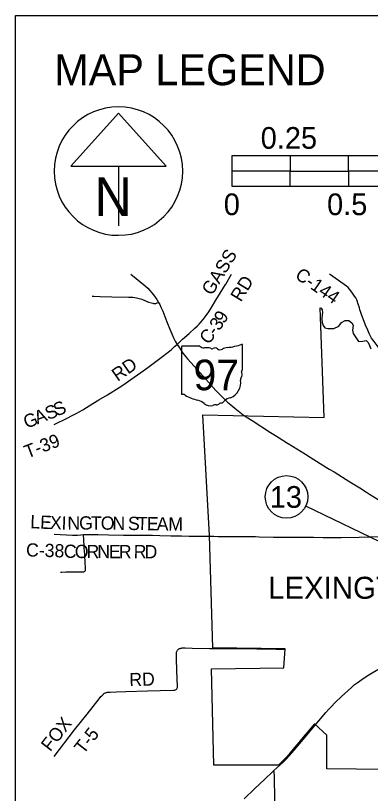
# Model space of a CAD drawing. Extents: x 40529 to 41139, y 15164 to 15584.
# Drawn here: x 40528.7 to 40574.5, y 15483.8 to 15584.3 of the extents above; entities that cross this region are included whole.
import ezdxf

# ---------------------------------------------------------------- set-up
doc = ezdxf.new("R2010")
doc.units = 0
for name, color, linetype in [('GM_X_Corporation', 7, 'Continuous'), ('GM_X_Corporation_Text', 7, 'Continuous'), ('GM_X_County_Road', 7, 'Continuous'), ('GM_X_County_Road_Text', 7, 'Continuous'), ('GM_X_State_Route', 7, 'Continuous'), ('GM_X_State_Shield', 7, 'Continuous'), ('GM_X_Township_Road', 7, 'Continuous'), ('GM_X_Township_Road_Text', 7, 'Continuous'), ('GM_X_US_Route', 7, 'Continuous'), ('SC_Scratch1', 7, 'Continuous'), ('SH_Data', 7, 'Continuous'), ('SH_Text', 7, 'Continuous')]:
    doc.layers.add(name, color=color, linetype=linetype)

msp = doc.modelspace()

# ---------------------------------------------------------------- linework, layer by layer
at = {"layer": 'GM_X_Corporation'}
msp.add_lwpolyline([(40584.23, 15486.79), (40568.88, 15486.95), (40568.88, 15486.95), (40568.88, 15491.32), (40567.29, 15492.76), (40566.61, 15491.95), (40565.83, 15491.04), (40565.06, 15490.12), (40564.72, 15489.71), (40564.14, 15489.02), (40563.75, 15488.56), (40563.04, 15487.84), (40562.64, 15487.43), (40554.28, 15487.42), (40553.97, 15499.9), (40563.32, 15500.01), (40563.49, 15502.49), (40554.13, 15502.61), (40553.72, 15517.1), (40552.87, 15532.73), (40568.54, 15532.36), (40568, 15546.52), (40568.14, 15546.49), (40568.28, 15546.26), (40568.32, 15545.94), (40568.29, 15545.62), (40568.25, 15545.13), (40568.27, 15544.63), (40568.39, 15544.27), (40568.62, 15543.97), (40568.99, 15543.85), (40569.77, 15543.86), (40570.41, 15544.15), (40570.79, 15544.64), (40571.23, 15544.89), (40571.74, 15544.9), (40572.12, 15544.62), (40572.28, 15544.29), (40572.2, 15543.64), (40572.28, 15543.21), (40572.61, 15542.7), (40572.99, 15542.21), (40573.55, 15542.23), (40573.95, 15542.33), (40574.22, 15542.05), (40574.41, 15541.67), (40574.58, 15541.26)], dxfattribs=at)
at = {"layer": 'GM_X_County_Road'}
for p, q in [((40555.82, 15549.61), (40556.58, 15550.88)), ((40568.42, 15516.86), (40569.24, 15516.85))]:
    msp.add_line(p, q, dxfattribs=at)
for points in [[(40573.15, 15546.3), (40573.09, 15546.52), (40572.9, 15547.14), (40572.84, 15547.32), (40572.74, 15547.57), (40572.61, 15547.82), (40572.46, 15548.06), (40572.21, 15548.44), (40571.99, 15548.75), (40571.82, 15548.97), (40571.63, 15549.16), (40571.42, 15549.34), (40571.12, 15549.56), (40569.23, 15550.88)], [(40549.53, 15541.82), (40549.62, 15541.9), (40550.24, 15542.47), (40551.07, 15543.22), (40551.83, 15543.9), (40552.17, 15544.22), (40552.36, 15544.42), (40552.61, 15544.69), (40552.9, 15545.05), (40553.29, 15545.57), (40553.61, 15546.03), (40553.96, 15546.57), (40554.55, 15547.52), (40555.79, 15549.56), (40555.82, 15549.61)], [(40573.89, 15544.31), (40573.71, 15544.76), (40573.41, 15545.55), (40573.22, 15546.07), (40573.15, 15546.3)], [(40575.85, 15540.86), (40575.79, 15541.04), (40575.66, 15541.29), (40575.5, 15541.51), (40574.98, 15542.17), (40574.81, 15542.4), (40574.66, 15542.63), (40574.52, 15542.87), (40574.35, 15543.21), (40574.16, 15543.64), (40573.89, 15544.31)], [(40533.65, 15517.29), (40536.01, 15517.17), (40536.64, 15517.17), (40537.1, 15517.2), (40537.44, 15517.23)], [(40537.44, 15517.23), (40537.74, 15517.23), (40538.33, 15517.23), (40539.32, 15517.23), (40540.65, 15517.19), (40542.6, 15517.18), (40543.83, 15517.17), (40544.89, 15517.16), (40545.26, 15517.16), (40546.36, 15517.14), (40547.3, 15517.12), (40548.72, 15517.09), (40550.09, 15517.07), (40551.08, 15517.04), (40551.67, 15517.03), (40552.31, 15517.03), (40552.88, 15517.02), (40553.71, 15517.01)], [(40553.71, 15517.01), (40553.74, 15517.01), (40554.27, 15517.01), (40554.85, 15517), (40555.51, 15517), (40556.97, 15517)], [(40556.97, 15517), (40557.44, 15516.99), (40558.18, 15516.99), (40559.67, 15516.97), (40560.13, 15516.96), (40562, 15516.92), (40563.92, 15516.9)], [(40563.92, 15516.9), (40565.3, 15516.89), (40567.14, 15516.88), (40568.42, 15516.86)], [(40569.24, 15516.85), (40570.03, 15516.85), (40570.5, 15516.86), (40570.74, 15516.86)], [(40570.74, 15516.86), (40573.06, 15516.91), (40575.97, 15516.98), (40578.14, 15517.02), (40578.62, 15517.04)]]:
    msp.add_lwpolyline(points, dxfattribs=at)
at = {"layer": 'GM_X_State_Route'}
for points in [[(40543.56, 15550.88), (40545.38, 15549.37), (40545.73, 15549.06), (40545.99, 15548.8), (40546.24, 15548.52), (40546.48, 15548.23), (40546.7, 15547.93), (40546.91, 15547.62), (40547.1, 15547.3), (40547.13, 15547.24), (40547.28, 15546.97), (40547.44, 15546.63), (40547.67, 15546.12), (40547.95, 15545.43), (40548.22, 15544.73), (40548.59, 15543.77), (40548.84, 15543.17), (40549.07, 15542.67), (40549.28, 15542.25), (40549.53, 15541.82)], [(40549.53, 15541.82), (40549.66, 15541.61), (40549.91, 15541.22), (40550.17, 15540.83), (40550.45, 15540.46), (40550.87, 15539.96), (40551.3, 15539.47), (40552.11, 15538.57), (40553.23, 15537.32), (40554.54, 15535.87), (40555.12, 15535.26), (40555.65, 15534.74), (40556.05, 15534.35), (40556.47, 15533.99), (40556.97, 15533.57), (40557.63, 15533.05), (40558.08, 15532.72), (40558.46, 15532.46), (40559.21, 15532), (40559.24, 15531.98)], [(40559.24, 15531.98), (40561.61, 15530.44), (40562.02, 15530.18)], [(40562.02, 15530.18), (40562.72, 15529.75), (40563.81, 15529.05), (40563.88, 15529.01), (40565.56, 15527.96), (40566.12, 15527.61)], [(40566.12, 15527.61), (40566.74, 15527.23), (40567.18, 15526.95), (40569.19, 15525.71), (40569.84, 15525.33), (40571.87, 15524.04), (40573.14, 15523.26), (40574, 15522.73), (40574.41, 15522.47), (40576.06, 15521.44), (40576.19, 15521.36)]]:
    msp.add_lwpolyline(points, dxfattribs=at)
at = {"layer": 'GM_X_State_Shield'}
for p, q in [((40552.48, 15541.57), (40550.16, 15541.57)), ((40558, 15538.58), (40558, 15541.72)), ((40550.09, 15541.47), (40550.09, 15535.46)), ((40558, 15538.58), (40558, 15538.58))]:
    msp.add_line(p, q, dxfattribs=at)
for centre, radius, start, end in [((40550.18, 15541.48), 0.0916, 98.1301, 188.1301), ((40553.03, 15542.27), 0.889, 231.6195, 271.1119), ((40555.18, 15549.76), 8.39, 275.8445, 288.9065), ((40557.91, 15541.73), 0.0881, 351.8621, 97.738), ((40553.33, 15538.2), 3.19, 80.4867, 94.9883), ((40554.05, 15541.51), 0.256, 219.7921, 297.1024), ((40554.43, 15540.82), 0.533, 54.4667, 119.1411), ((40555.12, 15541.77), 0.641, 233.8562, 294.8282), ((40556.25, 15539.74), 1.69, 97.3462, 120.7689), ((40557.9, 15538.57), 0.0942, 289.6038, 7.7341), ((40558.31, 15537.27), 0.595, 136.8065, 186.9296), ((40557.98, 15538.35), 0.136, 107.944, 210.337), ((40557.11, 15537.95), 0.818, 340.033, 23.6496), ((40555.65, 15536.87), 2.1, 292.3089, 8.9858), ((40550.18, 15535.45), 0.0925, 171.9584, 258.3066), ((40550.19, 15536.07), 0.706, 267.339, 280.6039), ((40550.34, 15535.12), 0.254, 29.7484, 93.2717), ((40553.55, 15540.51), 6.06, 240.4129, 257.1985), ((40551.74, 15532.77), 1.9, 47.1842, 75.836), ((40555.08, 15534.88), 0.678, 282.8732, 323.2771), ((40556.53, 15533.78), 1.15, 94.4031, 142.5768), ((40553.79, 15535.09), 1.2, 230.7004, 286.2918), ((40554.49, 15533.01), 0.988, 85.6951, 111.2099), ((40554.57, 15534.64), 0.641, 268.777, 315.5493), ((40555.15, 15534.06), 0.18, 65.7517, 132.6484)]:
    msp.add_arc(centre, radius, start, end, dxfattribs=at)
at = {"layer": 'GM_X_Township_Road'}
for points in [[(40538.57, 15548.05), (40538.76, 15548.04), (40539.6, 15548.02), (40541.09, 15547.95), (40543.24, 15547.91), (40543.8, 15547.9), (40544.08, 15547.88), (40544.26, 15547.85), (40544.45, 15547.81), (40544.62, 15547.76), (40544.97, 15547.64), (40545.84, 15547.29), (40546.2, 15547.17), (40546.38, 15547.13), (40546.48, 15547.11), (40546.57, 15547.1), (40546.67, 15547.11), (40546.77, 15547.12), (40546.86, 15547.14), (40546.95, 15547.17), (40547.13, 15547.24)], [(40533.65, 15531.48), (40535.4, 15532.32), (40535.98, 15532.62), (40536.55, 15532.93), (40536.87, 15533.12), (40537.34, 15533.37), (40538.62, 15534.16), (40539.42, 15534.64), (40540.53, 15535.31), (40542.03, 15536.24), (40542.65, 15536.65), (40543.57, 15537.28), (40544.85, 15538.2), (40545.76, 15538.85), (40547.62, 15540.25), (40548.2, 15540.7), (40548.74, 15541.13), (40549.21, 15541.53), (40549.53, 15541.82)], [(40534.48, 15512.39), (40534.63, 15512.39), (40535.13, 15512.4), (40535.48, 15512.4), (40536.32, 15512.41), (40536.75, 15512.4), (40537.22, 15512.4), (40537.37, 15512.41), (40537.46, 15512.43), (40537.53, 15512.45), (40537.58, 15512.48), (40537.62, 15512.52), (40537.65, 15512.56), (40537.67, 15512.61), (40537.68, 15512.69), (40537.68, 15512.82), (40537.64, 15513.77), (40537.6, 15514.42), (40537.59, 15514.64), (40537.56, 15515.12), (40537.53, 15515.48), (40537.51, 15515.77), (40537.44, 15517.23)], [(40533.65, 15488.57), (40536.27, 15491.99), (40537.89, 15494.03), (40539.44, 15496.01), (40539.68, 15496.3), (40539.87, 15496.5), (40540, 15496.62), (40540.08, 15496.68), (40540.15, 15496.73), (40540.24, 15496.77), (40540.32, 15496.8), (40540.41, 15496.83), (40540.49, 15496.85), (40540.68, 15496.88), (40540.86, 15496.89), (40541.7, 15496.91), (40542.91, 15496.94), (40545.7, 15497.02), (40548.96, 15497.12), (40549.15, 15497.13), (40549.24, 15497.14), (40549.33, 15497.18), (40549.42, 15497.23), (40549.49, 15497.3), (40549.53, 15497.39), (40549.56, 15497.48), (40549.57, 15497.58), (40549.57, 15497.67), (40549.54, 15498.51), (40549.53, 15498.79), (40549.51, 15499.44), (40549.44, 15501.4), (40549.44, 15501.77), (40549.46, 15501.95), (40549.47, 15502.04), (40549.5, 15502.12), (40549.53, 15502.2), (40549.58, 15502.28), (40549.63, 15502.35), (40549.7, 15502.41), (40549.77, 15502.46), (40549.85, 15502.5), (40549.93, 15502.53), (40550.02, 15502.56), (40550.11, 15502.57), (40550.2, 15502.58), (40550.56, 15502.58), (40551.49, 15502.57), (40553.72, 15502.53), (40554.12, 15502.53)], [(40554.12, 15502.53), (40554.15, 15502.53), (40554.62, 15502.53), (40556.48, 15502.51), (40557.6, 15502.5), (40559.83, 15502.47), (40561.32, 15502.46), (40561.41, 15502.45), (40562.34, 15502.42), (40562.83, 15502.43), (40563.5, 15502.41), (40563.54, 15502.41)], [(40562.22, 15481.38), (40562.15, 15483.86), (40562.11, 15485.08), (40562.1, 15486.1), (40562.08, 15486.38), (40562.06, 15486.56), (40562.05, 15486.74)]]:
    msp.add_lwpolyline(points, dxfattribs=at)
at = {"layer": 'GM_X_US_Route'}
for points in [[(40567.86, 15493.17), (40568.75, 15494.23), (40569.12, 15494.66), (40569.15, 15494.68), (40569.43, 15494.99), (40569.94, 15495.52), (40570.78, 15496.29), (40572.08, 15497.48), (40572.43, 15497.8), (40572.78, 15498.09), (40573.1, 15498.31), (40573.71, 15498.73), (40573.91, 15498.85), (40574.1, 15498.97), (40574.52, 15499.24), (40575.46, 15499.81), (40575.97, 15500.12)], [(40562.81, 15487.43), (40563.29, 15487.88), (40563.62, 15488.21), (40564.06, 15488.69), (40564.67, 15489.39), (40566.31, 15491.29), (40567.36, 15492.59), (40567.86, 15493.17)], [(40558.19, 15483.07), (40559.52, 15484.36), (40560.86, 15485.64), (40561.85, 15486.56), (40562.05, 15486.74), (40562.81, 15487.43)]]:
    msp.add_lwpolyline(points, dxfattribs=at)
at = {"layer": 'SC_Scratch1'}
msp.add_lwpolyline([(40528.65, 15584.31), (41138.65, 15584.31), (41138.65, 15164.31), (40528.65, 15164.31)], close=True, dxfattribs=at)
at = {"layer": 'SH_Data'}
for p, q in [((40541.95, 15571.69), (40535.8, 15564.86)), ((40548.1, 15564.86), (40541.95, 15571.69)), ((40535.8, 15564.86), (40548.1, 15564.86)), ((40541.95, 15564.86), (40541.95, 15557.13)), ((40541.95, 15564.21), (40541.95, 15564.21)), ((40541.95, 15564.21), (40541.95, 15564.21)), ((40578.52, 15514.93), (40566.15, 15520.9))]:
    msp.add_line(p, q, dxfattribs=at)
for points in [[(40556.66, 15566.21), (40586.66, 15566.21), (40586.66, 15562.21), (40556.66, 15562.21)], [(40556.66, 15566.21), (40564.16, 15566.21), (40564.16, 15564.21), (40556.66, 15564.21)], [(40571.66, 15566.21), (40579.16, 15566.21), (40579.16, 15564.21), (40571.66, 15564.21)], [(40564.16, 15564.21), (40571.66, 15564.21), (40571.66, 15562.21), (40564.16, 15562.21)]]:
    msp.add_lwpolyline(points, close=True, dxfattribs=at)
msp.add_arc((40541.95, 15564.21), 8.3, 90.0165, 90, dxfattribs=at)
at = {"layer": 'SH_Text'}
msp.add_circle((40563.67, 15522.1), 2.75, dxfattribs=at)

# ---------------------------------------------------------------- texts
at = {"layer": 'GM_X_Corporation_Text'}
msp.add_text('LEXINGTON', height=2.841, rotation=0, dxfattribs=at).set_placement((40561.29, 15508.94))
at = {"layer": 'GM_X_County_Road_Text'}
for s, height, rotation, p in [('GASS', 1.706, 58.4961, (40554.04, 15548.03)), ('C-144', 1.706, 325.6321, (40564.65, 15550.45)), ('RD', 1.706, 58.6191, (40557.77, 15547.21)), ('9', 1.71, 57.8041, (40555.6, 15544.4)), ('3', 1.71, 55.9512, (40554.98, 15543.48)), ('C', 1.71, 49.1408, (40553.53, 15541.7)), ('-', 1.71, 53.4162, (40554.52, 15542.86)), ('L', 1.71, 357.6465, (40530.52, 15518.06)), ('E', 1.71, 357.6478, (40531.8, 15518)), ('X', 1.71, 357.6534, (40533.07, 15517.95)), ('I', 1.71, 357.6914, (40534.57, 15517.89)), ('N', 1.71, 0.2027, (40535.35, 15517.86)), ('G', 1.71, 1.0421, (40536.88, 15517.87)), ('T', 1.71, 359.2757, (40538.37, 15517.89)), ('O', 1.71, 359.2568, (40539.65, 15517.88)), ('N', 1.71, 359.2623, (40541.15, 15517.86)), ('S', 1.71, 359.2588, (40543.17, 15517.83)), ('T', 1.71, 359.2597, (40544.33, 15517.82)), ('E', 1.71, 359.2597, (40545.6, 15517.8)), ('A', 1.71, 359.2586, (40546.88, 15517.78)), ('M', 1.71, 359.2599, (40548.38, 15517.76)), ('C-38', 1.706, 358.3263, (40529.99, 15514.42)), ('C', 1.71, 358.2395, (40534.86, 15514.25)), ('O', 1.71, 359.5307, (40536.3, 15514.21)), ('R', 1.71, 359.8067, (40537.81, 15514.19)), ('N', 1.71, 359.8629, (40539.21, 15514.19)), ('E', 1.71, 359.8704, (40540.72, 15514.18)), ('R', 1.71, 359.8712, (40541.99, 15514.18)), ('R', 1.71, 359.8689, (40543.92, 15514.18)), ('D', 1.71, 359.8689, (40545.32, 15514.17))]:
    msp.add_text(s, height=height, rotation=rotation, dxfattribs=at).set_placement(p)
at = {"layer": 'GM_X_State_Shield'}
msp.add_text('97', height=3.955, dxfattribs=at).set_placement((40551.65, 15535.89))
at = {"layer": 'GM_X_Township_Road_Text'}
for s, height, rotation, p in [('RD', 1.706, 34.8389, (40541.84, 15536.96)), ('S', 1.71, 23.7645, (40533.99, 15532.46)), ('S', 1.71, 21.6949, (40532.86, 15532.01)), ('G', 1.71, 21.6228, (40530.07, 15530.9)), ('A', 1.71, 21.6228, (40531.46, 15531.46)), ('T-39', 1.706, 20.9012, (40530.17, 15527.05)), ('RD', 1.706, 1.4806, (40543.37, 15497.64)), ('FOX', 1.706, 52.0956, (40533.14, 15489.09)), ('T-5', 1.706, 51.7904, (40537.43, 15488.75))]:
    msp.add_text(s, height=height, rotation=rotation, dxfattribs=at).set_placement(p)
at = {"layer": 'SH_Data'}
for s, height, p in [('0.25', 2.8, (40560.33, 15567.1)), ('N', 5, (40538.84, 15558.39)), ('0', 2.8, (40555.56, 15558.52)), ('0.5', 2.8, (40568.91, 15558.52))]:
    msp.add_text(s, height=height, dxfattribs=at).set_placement(p)
at = {"layer": 'SH_Text'}
for s, height, p in [('MAP LEGEND                                                                                                                                                                   ', 4, (40533.65, 15575.31)), ('13', 2.8, (40561.5, 15520.7))]:
    msp.add_text(s, height=height, dxfattribs=at).set_placement(p)

doc.saveas('drawing.dxf')
